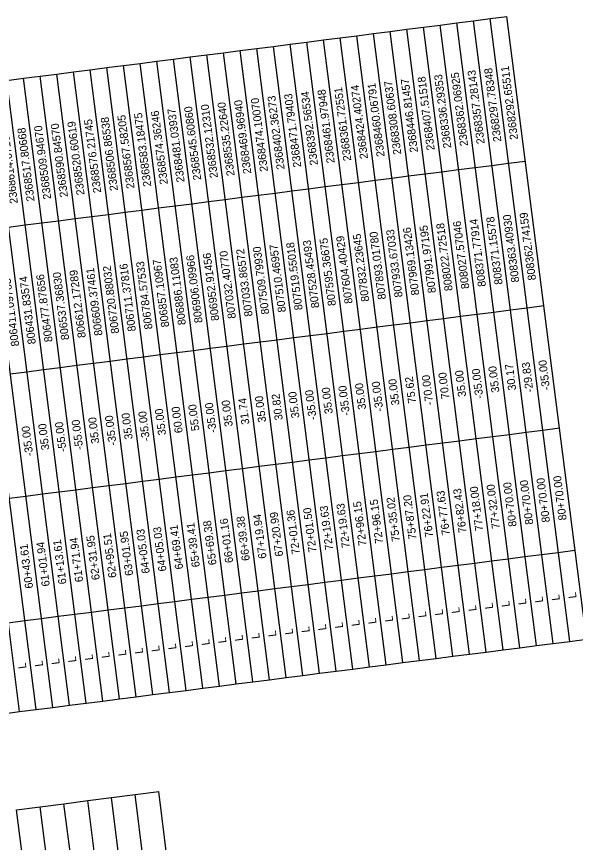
# Model space of a CAD drawing. Extents: x 2364621 to 2374814, y 792603 to 806745.
# Drawn here: x 2369750 to 2371409, y 798784 to 801235 of the extents above; entities that cross this region are included whole.
import ezdxf

# ---------------------------------------------------------------- set-up
doc = ezdxf.new("R2010")
doc.units = 0
doc.layers.add('CTL Sheet Table Cell', color=7, linetype='Continuous')
doc.layers.add('CTL Sheet Text', color=7, linetype='Continuous')

msp = doc.modelspace()

# ---------------------------------------------------------------- linework, layer by layer
at = {"layer": 'CTL Sheet Table Cell'}
for p, q in [((2371106.7, 801222.7), (2371156.1, 801229)), ((2371156.1, 801229), (2371205.6, 801235.3)), ((2371392.1, 799381.2), (2371156.1, 801229)), ((2371441.6, 799387.5), (2371205.6, 801235.3)), ((2370908.7, 801197.4), (2370958.2, 801203.7)), ((2370958.2, 801203.7), (2371007.7, 801210)), ((2371194.2, 799355.9), (2370958.2, 801203.7)), ((2371007.7, 801210), (2371057.2, 801216.3)), ((2371243.7, 799362.2), (2371007.7, 801210)), ((2371057.2, 801216.3), (2371106.7, 801222.7)), ((2371293.2, 799368.6), (2371057.2, 801216.3)), ((2371342.7, 799374.9), (2371106.7, 801222.7)), ((2370710.7, 801172.1), (2370760.2, 801178.4)), ((2370760.2, 801178.4), (2370809.7, 801184.7)), ((2370996.2, 799330.6), (2370760.2, 801178.4)), ((2370809.7, 801184.7), (2370859.2, 801191.1)), ((2371045.7, 799337), (2370809.7, 801184.7)), ((2370859.2, 801191.1), (2370908.7, 801197.4)), ((2371095.2, 799343.3), (2370859.2, 801191.1)), ((2371144.7, 799349.6), (2370908.7, 801197.4)), ((2370562.2, 801153.1), (2370611.7, 801159.4)), ((2370611.7, 801159.4), (2370661.2, 801165.8)), ((2370847.7, 799311.7), (2370611.7, 801159.4)), ((2370661.2, 801165.8), (2370710.7, 801172.1)), ((2370897.2, 799318), (2370661.2, 801165.8)), ((2370946.7, 799324.3), (2370710.7, 801172.1)), ((2370364.2, 801127.8), (2370413.7, 801134.2)), ((2370413.7, 801134.2), (2370463.2, 801140.5)), ((2370649.7, 799286.4), (2370413.7, 801134.2)), ((2370463.2, 801140.5), (2370512.7, 801146.8)), ((2370699.2, 799292.7), (2370463.2, 801140.5)), ((2370512.7, 801146.8), (2370562.2, 801153.1)), ((2370748.7, 799299), (2370512.7, 801146.8)), ((2370798.2, 799305.4), (2370562.2, 801153.1)), ((2370166.3, 801102.6), (2370215.8, 801108.9)), ((2370215.8, 801108.9), (2370265.3, 801115.2)), ((2370451.8, 799261.1), (2370215.8, 801108.9)), ((2370265.3, 801115.2), (2370314.8, 801121.5)), ((2370501.3, 799267.4), (2370265.3, 801115.2)), ((2370314.8, 801121.5), (2370364.2, 801127.8)), ((2370550.7, 799273.7), (2370314.8, 801121.5)), ((2370600.2, 799280.1), (2370364.2, 801127.8)), ((2369968.3, 801077.3), (2370017.8, 801083.6)), ((2370017.8, 801083.6), (2370067.3, 801089.9)), ((2370253.8, 799235.8), (2370017.8, 801083.6)), ((2370067.3, 801089.9), (2370116.8, 801096.2)), ((2370303.3, 799242.1), (2370067.3, 801089.9)), ((2370116.8, 801096.2), (2370166.3, 801102.6)), ((2370352.8, 799248.5), (2370116.8, 801096.2)), ((2370402.3, 799254.8), (2370166.3, 801102.6)), ((2369770.3, 801052), (2369819.8, 801058.3)), ((2369819.8, 801058.3), (2369869.3, 801064.6)), ((2370055.8, 799210.5), (2369819.8, 801058.3)), ((2369869.3, 801064.6), (2369918.8, 801070.9)), ((2370105.3, 799216.9), (2369869.3, 801064.6)), ((2369918.8, 801070.9), (2369968.3, 801077.3)), ((2370154.8, 799223.2), (2369918.8, 801070.9)), ((2370204.3, 799229.5), (2369968.3, 801077.3)), ((2369857.8, 799185.2), (2369621.8, 801033)), ((2369907.3, 799191.6), (2369671.3, 801039.3)), ((2369720.8, 801045.7), (2369770.3, 801052)), ((2369956.8, 799197.9), (2369720.8, 801045.7)), ((2370006.3, 799204.2), (2369770.3, 801052)), ((2369758.8, 799172.6), (2369522.8, 801020.4)), ((2369808.3, 799178.9), (2369572.3, 801026.7)), ((2371062.5, 800781.1), (2371111.9, 800787.4)), ((2371111.9, 800787.4), (2371161.4, 800793.7)), ((2371161.4, 800793.7), (2371210.9, 800800)), ((2371210.9, 800800), (2371260.4, 800806.4)), ((2370864.5, 800755.8), (2370914, 800762.1)), ((2370914, 800762.1), (2370963.5, 800768.4)), ((2370963.5, 800768.4), (2371013, 800774.7)), ((2371013, 800774.7), (2371062.5, 800781.1)), ((2370716, 800736.8), (2370765.5, 800743.1)), ((2370765.5, 800743.1), (2370815, 800749.5)), ((2370815, 800749.5), (2370864.5, 800755.8)), ((2370518, 800711.5), (2370567.5, 800717.9)), ((2370567.5, 800717.9), (2370617, 800724.2)), ((2370617, 800724.2), (2370666.5, 800730.5)), ((2370666.5, 800730.5), (2370716, 800736.8)), ((2370320, 800686.2), (2370369.5, 800692.6)), ((2370369.5, 800692.6), (2370419, 800698.9)), ((2370419, 800698.9), (2370468.5, 800705.2)), ((2370468.5, 800705.2), (2370518, 800711.5)), ((2370122.1, 800661), (2370171.6, 800667.3)), ((2370171.6, 800667.3), (2370221.1, 800673.6)), ((2370221.1, 800673.6), (2370270.5, 800679.9)), ((2370270.5, 800679.9), (2370320, 800686.2)), ((2369924.1, 800635.7), (2369973.6, 800642)), ((2369973.6, 800642), (2370023.1, 800648.3)), ((2370023.1, 800648.3), (2370072.6, 800654.6)), ((2370072.6, 800654.6), (2370122.1, 800661)), ((2369726.1, 800610.4), (2369775.6, 800616.7)), ((2369775.6, 800616.7), (2369825.1, 800623)), ((2369825.1, 800623), (2369874.6, 800629.4)), ((2369874.6, 800629.4), (2369924.1, 800635.7)), ((2371216.2, 800364.8), (2371265.7, 800371.1)), ((2371265.7, 800371.1), (2371315.2, 800377.4)), ((2371018.2, 800339.5), (2371067.7, 800345.8)), ((2371067.7, 800345.8), (2371117.2, 800352.1)), ((2371117.2, 800352.1), (2371166.7, 800358.4)), ((2371166.7, 800358.4), (2371216.2, 800364.8)), ((2370820.3, 800314.2), (2370869.8, 800320.5)), ((2370869.8, 800320.5), (2370919.3, 800326.8)), ((2370919.3, 800326.8), (2370968.8, 800333.2)), ((2370968.8, 800333.2), (2371018.2, 800339.5)), ((2370671.8, 800295.2), (2370721.3, 800301.6)), ((2370721.3, 800301.6), (2370770.8, 800307.9)), ((2370770.8, 800307.9), (2370820.3, 800314.2)), ((2370473.8, 800269.9), (2370523.3, 800276.3)), ((2370523.3, 800276.3), (2370572.8, 800282.6)), ((2370572.8, 800282.6), (2370622.3, 800288.9)), ((2370622.3, 800288.9), (2370671.8, 800295.2)), ((2370275.8, 800244.7), (2370325.3, 800251)), ((2370325.3, 800251), (2370374.8, 800257.3)), ((2370374.8, 800257.3), (2370424.3, 800263.6)), ((2370424.3, 800263.6), (2370473.8, 800269.9)), ((2370077.9, 800219.4), (2370127.4, 800225.7)), ((2370127.4, 800225.7), (2370176.9, 800232)), ((2370176.9, 800232), (2370226.3, 800238.3)), ((2370226.3, 800238.3), (2370275.8, 800244.7)), ((2369879.9, 800194.1), (2369929.4, 800200.4)), ((2369929.4, 800200.4), (2369978.9, 800206.7)), ((2369978.9, 800206.7), (2370028.4, 800213.1)), ((2370028.4, 800213.1), (2370077.9, 800219.4)), ((2369731.4, 800175.1), (2369780.9, 800181.4)), ((2369780.9, 800181.4), (2369830.4, 800187.8)), ((2369830.4, 800187.8), (2369879.9, 800194.1)), ((2371262.6, 800001.8), (2371312.1, 800008.1)), ((2371312.1, 800008.1), (2371361.6, 800014.5)), ((2371064.6, 799976.5), (2371114.1, 799982.8)), ((2371114.1, 799982.8), (2371163.6, 799989.2)), ((2371163.6, 799989.2), (2371213.1, 799995.5)), ((2371213.1, 799995.5), (2371262.6, 800001.8)), ((2370866.6, 799951.2), (2370916.1, 799957.6)), ((2370916.1, 799957.6), (2370965.6, 799963.9)), ((2370965.6, 799963.9), (2371015.1, 799970.2)), ((2371015.1, 799970.2), (2371064.6, 799976.5)), ((2370668.7, 799926), (2370718.1, 799932.3)), ((2370718.1, 799932.3), (2370767.6, 799938.6)), ((2370767.6, 799938.6), (2370817.1, 799944.9)), ((2370817.1, 799944.9), (2370866.6, 799951.2)), ((2370470.7, 799900.7), (2370520.2, 799907)), ((2370520.2, 799907), (2370569.7, 799913.3)), ((2370569.7, 799913.3), (2370619.2, 799919.6)), ((2370619.2, 799919.6), (2370668.7, 799926)), ((2370272.7, 799875.4), (2370322.2, 799881.7)), ((2370322.2, 799881.7), (2370371.7, 799888)), ((2370371.7, 799888), (2370421.2, 799894.3)), ((2370421.2, 799894.3), (2370470.7, 799900.7)), ((2370074.7, 799850.1), (2370124.2, 799856.4)), ((2370124.2, 799856.4), (2370173.7, 799862.7)), ((2370173.7, 799862.7), (2370223.2, 799869.1)), ((2370223.2, 799869.1), (2370272.7, 799875.4)), ((2369876.8, 799824.8), (2369926.2, 799831.1)), ((2369926.2, 799831.1), (2369975.7, 799837.5)), ((2369975.7, 799837.5), (2370025.2, 799843.8)), ((2370025.2, 799843.8), (2370074.7, 799850.1)), ((2369728.3, 799805.8), (2369777.8, 799812.2)), ((2369777.8, 799812.2), (2369827.3, 799818.5)), ((2369827.3, 799818.5), (2369876.8, 799824.8)), ((2371259.4, 799632.5), (2371308.9, 799638.9)), ((2371308.9, 799638.9), (2371358.4, 799645.2)), ((2371358.4, 799645.2), (2371407.9, 799651.5)), ((2371061.5, 799607.2), (2371111, 799613.6)), ((2371111, 799613.6), (2371160.5, 799619.9)), ((2371160.5, 799619.9), (2371209.9, 799626.2)), ((2371209.9, 799626.2), (2371259.4, 799632.5)), ((2370863.5, 799582), (2370913, 799588.3)), ((2370913, 799588.3), (2370962.5, 799594.6)), ((2370962.5, 799594.6), (2371012, 799600.9)), ((2371012, 799600.9), (2371061.5, 799607.2)), ((2370665.5, 799556.7), (2370715, 799563)), ((2370715, 799563), (2370764.5, 799569.3)), ((2370764.5, 799569.3), (2370814, 799575.6)), ((2370814, 799575.6), (2370863.5, 799582)), ((2370467.5, 799531.4), (2370517, 799537.7)), ((2370517, 799537.7), (2370566.5, 799544)), ((2370566.5, 799544), (2370616, 799550.4)), ((2370616, 799550.4), (2370665.5, 799556.7)), ((2370269.6, 799506.1), (2370319.1, 799512.4)), ((2370319.1, 799512.4), (2370368.6, 799518.7)), ((2370368.6, 799518.7), (2370418, 799525.1)), ((2370418, 799525.1), (2370467.5, 799531.4)), ((2370121.1, 799487.1), (2370170.6, 799493.5)), ((2370170.6, 799493.5), (2370220.1, 799499.8)), ((2370220.1, 799499.8), (2370269.6, 799506.1)), ((2369923.1, 799461.9), (2369972.6, 799468.2)), ((2369972.6, 799468.2), (2370022.1, 799474.5)), ((2370022.1, 799474.5), (2370071.6, 799480.8)), ((2370071.6, 799480.8), (2370121.1, 799487.1)), ((2369725.1, 799436.6), (2369774.6, 799442.9)), ((2369774.6, 799442.9), (2369824.1, 799449.2)), ((2369824.1, 799449.2), (2369873.6, 799455.5)), ((2369873.6, 799455.5), (2369923.1, 799461.9)), ((2371243.7, 799362.2), (2371293.2, 799368.6)), ((2371293.2, 799368.6), (2371342.7, 799374.9)), ((2371342.7, 799374.9), (2371392.1, 799381.2)), ((2371392.1, 799381.2), (2371441.6, 799387.5)), ((2371045.7, 799337), (2371095.2, 799343.3)), ((2371095.2, 799343.3), (2371144.7, 799349.6)), ((2371144.7, 799349.6), (2371194.2, 799355.9)), ((2371194.2, 799355.9), (2371243.7, 799362.2)), ((2370847.7, 799311.7), (2370897.2, 799318)), ((2370897.2, 799318), (2370946.7, 799324.3)), ((2370946.7, 799324.3), (2370996.2, 799330.6)), ((2370996.2, 799330.6), (2371045.7, 799337)), ((2370649.7, 799286.4), (2370699.2, 799292.7)), ((2370699.2, 799292.7), (2370748.7, 799299)), ((2370748.7, 799299), (2370798.2, 799305.4)), ((2370798.2, 799305.4), (2370847.7, 799311.7)), ((2370451.8, 799261.1), (2370501.3, 799267.4)), ((2370501.3, 799267.4), (2370550.7, 799273.7)), ((2370550.7, 799273.7), (2370600.2, 799280.1)), ((2370600.2, 799280.1), (2370649.7, 799286.4)), ((2370253.8, 799235.8), (2370303.3, 799242.1)), ((2370303.3, 799242.1), (2370352.8, 799248.5)), ((2370352.8, 799248.5), (2370402.3, 799254.8)), ((2370402.3, 799254.8), (2370451.8, 799261.1)), ((2370105.3, 799216.9), (2370154.8, 799223.2)), ((2370154.8, 799223.2), (2370204.3, 799229.5)), ((2370204.3, 799229.5), (2370253.8, 799235.8)), ((2369907.3, 799191.6), (2369956.8, 799197.9)), ((2369956.8, 799197.9), (2370006.3, 799204.2)), ((2370006.3, 799204.2), (2370055.8, 799210.5)), ((2370055.8, 799210.5), (2370105.3, 799216.9)), ((2369709.4, 799166.3), (2369758.8, 799172.6)), ((2369758.8, 799172.6), (2369808.3, 799178.9)), ((2369808.3, 799178.9), (2369857.8, 799185.2)), ((2369857.8, 799185.2), (2369907.3, 799191.6)), ((2370031.5, 798917.4), (2370101.8, 798926.4)), ((2370101.8, 798926.4), (2370172.1, 798935.4)), ((2370353.2, 796957.9), (2370101.8, 798926.4)), ((2370423.5, 796966.9), (2370172.1, 798935.4)), ((2369820.6, 798890.5), (2369890.9, 798899.5)), ((2369890.9, 798899.5), (2369961.2, 798908.5)), ((2370142.3, 796931), (2369890.9, 798899.5)), ((2369961.2, 798908.5), (2370031.5, 798917.4)), ((2370212.6, 796939.9), (2369961.2, 798908.5)), ((2370282.9, 796948.9), (2370031.5, 798917.4)), ((2369750.3, 798881.5), (2369820.6, 798890.5)), ((2370001.7, 796913), (2369750.3, 798881.5)), ((2370072, 796922), (2369820.6, 798890.5))]:
    msp.add_line(p, q, dxfattribs=at)

# ---------------------------------------------------------------- texts
at = {"layer": 'CTL Sheet Text'}
for s, height, p in [('2368297.78348', 23.76, (2371189.5, 800864.8)), ('2368292.65511', 23.76, (2371239, 800871.1)), ('2368407.51518', 23.76, (2370991.5, 800839.5)), ('2368336.29353', 23.76, (2371041, 800845.8)), ('2368362.06925', 23.76, (2371090.5, 800852.1)), ('2368357.28143', 23.76, (2371140, 800858.4)), ('2368424.40274', 23.76, (2370793.5, 800814.2)), ('2368460.06791', 23.76, (2370843, 800820.5)), ('2368308.60637', 23.76, (2370892.5, 800826.8)), ('2368446.81457', 23.76, (2370942, 800833.2)), ('2368392.56534', 23.76, (2370645.1, 800795.2)), ('2368461.97948', 23.76, (2370694.6, 800801.5)), ('2368361.72551', 23.76, (2370744, 800807.9)), ('2368469.96940', 23.76, (2370447.1, 800769.9)), ('2368474.10070', 23.76, (2370496.6, 800776.3)), ('2368402.36273', 23.76, (2370546.1, 800782.6)), ('2368471.79403', 23.76, (2370595.6, 800788.9)), ('2368481.03937', 23.76, (2370249.1, 800744.7)), ('2368545.60860', 23.76, (2370298.6, 800751)), ('2368532.12310', 23.76, (2370348.1, 800757.3)), ('2368535.22640', 23.76, (2370397.6, 800763.6)), ('2368506.86538', 23.76, (2370051.1, 800719.4)), ('2368567.58205', 23.76, (2370100.6, 800725.7)), ('2368583.18475', 23.76, (2370150.1, 800732)), ('2368574.36246', 23.76, (2370199.6, 800738.3)), ('2368509.94670', 23.76, (2369853.2, 800694.1)), ('2368590.84570', 23.76, (2369902.7, 800700.4)), ('2368520.60619', 23.76, (2369952.1, 800706.7)), ('2368576.21745', 23.76, (2370001.6, 800713)), ('2368614.67163', 23.76, (2369754.2, 800681.4)), ('2368517.80668', 23.76, (2369803.7, 800687.8)), ('808371.15578', 23.76, (2371193.3, 800441.2)), ('808363.40930', 23.76, (2371242.8, 800447.5)), ('808362.74159', 23.76, (2371292.3, 800453.8)), ('807991.97195', 23.76, (2370995.3, 800415.9)), ('808022.72518', 23.76, (2371044.8, 800422.2)), ('808027.57046', 23.76, (2371094.3, 800428.5)), ('808371.77914', 23.76, (2371143.8, 800434.9)), ('807832.23645', 23.76, (2370797.3, 800390.6)), ('807893.01780', 23.76, (2370846.8, 800396.9)), ('807933.67033', 23.76, (2370896.3, 800403.3)), ('807969.13426', 23.76, (2370945.8, 800409.6)), ('807528.45493', 23.76, (2370648.9, 800371.6)), ('807595.36675', 23.76, (2370698.4, 800378)), ('807604.40429', 23.76, (2370747.8, 800384.3)), ('807033.86572', 23.76, (2370450.9, 800346.4)), ('807509.79930', 23.76, (2370500.4, 800352.7)), ('807510.46957', 23.76, (2370549.9, 800359)), ('807519.55018', 23.76, (2370599.4, 800365.3)), ('806886.11083', 23.76, (2370252.9, 800321.1)), ('806906.09966', 23.76, (2370302.4, 800327.4)), ('806952.91456', 23.76, (2370351.9, 800333.7)), ('807032.40770', 23.76, (2370401.4, 800340)), ('806720.88032', 23.76, (2370054.9, 800295.8)), ('806711.37816', 23.76, (2370104.4, 800302.1)), ('806784.57533', 23.76, (2370153.9, 800308.4)), ('806857.10967', 23.76, (2370203.4, 800314.8)), ('806477.87656', 23.76, (2369857, 800270.5)), ('806537.36830', 23.76, (2369906.4, 800276.8)), ('806612.17289', 23.76, (2369955.9, 800283.1)), ('806609.37461', 23.76, (2370005.4, 800289.5)), ('806411.09763', 23.76, (2369758, 800257.9)), ('806431.83574', 23.76, (2369807.5, 800264.2)), ('30.17', 23.76, (2371233.4, 800127.1)), ('-29.83', 23.76, (2371284.4, 800121.7)), ('-35.00', 23.76, (2371333.9, 800128)), ('70.00', 23.76, (2371035.4, 800101.8)), ('35.00', 23.76, (2371084.9, 800108.1)), ('-35.00', 23.76, (2371135.9, 800102.7)), ('35.00', 23.76, (2371183.9, 800120.7)), ('-35.00', 23.76, (2370839, 800064.8)), ('35.00', 23.76, (2370887, 800082.8)), ('75.62', 23.76, (2370936.4, 800089.1)), ('-70.00', 23.76, (2370987.4, 800083.8)), ('-35.00', 23.76, (2370641, 800039.5)), ('35.00', 23.76, (2370689, 800057.5)), ('-35.00', 23.76, (2370740, 800052.2)), ('35.00', 23.76, (2370788, 800070.2)), ('31.74', 23.76, (2370441.5, 800025.9)), ('35.00', 23.76, (2370491, 800032.3)), ('30.82', 23.76, (2370540.5, 800038.6)), ('35.00', 23.76, (2370590, 800044.9)), ('60.00', 23.76, (2370243.5, 800000.6)), ('55.00', 23.76, (2370293, 800007)), ('-35.00', 23.76, (2370344, 800001.6)), ('35.00', 23.76, (2370392, 800019.6)), ('-35.00', 23.76, (2370047, 799963.7)), ('35.00', 23.76, (2370095, 799981.7)), ('-35.00', 23.76, (2370146, 799976.3)), ('35.00', 23.76, (2370194, 799994.3)), ('35.00', 23.76, (2369847.6, 799950.1)), ('-55.00', 23.76, (2369898.6, 799944.7)), ('-55.00', 23.76, (2369948.1, 799951)), ('35.00', 23.76, (2369996.1, 799969)), ('-35.00', 23.76, (2369799.6, 799932.1)), ('80+70.00', 23.76, (2371284.2, 799729)), ('80+70.00', 23.76, (2371333.7, 799735.4)), ('80+70.00', 23.76, (2371383.2, 799741.7)), ('76+82.43', 23.76, (2371086.3, 799703.8)), ('77+18.00', 23.76, (2371135.8, 799710.1)), ('77+32.00', 23.76, (2371185.3, 799716.4)), ('80+70.00', 23.76, (2371234.8, 799722.7)), ('75+35.02', 23.76, (2370888.3, 799678.5)), ('75+87.20', 23.76, (2370937.8, 799684.8)), ('76+22.91', 23.76, (2370987.3, 799691.1)), ('76+77.63', 23.76, (2371036.8, 799697.4)), ('72+19.63', 23.76, (2370690.3, 799653.2)), ('72+19.63', 23.76, (2370739.8, 799659.5)), ('72+96.15', 23.76, (2370789.3, 799665.8)), ('72+96.15', 23.76, (2370838.8, 799672.1)), ('67+19.94', 23.76, (2370492.3, 799627.9)), ('67+20.99', 23.76, (2370541.8, 799634.2)), ('72+01.36', 23.76, (2370591.3, 799640.5)), ('72+01.50', 23.76, (2370640.8, 799646.9)), ('65+39.41', 23.76, (2370294.4, 799602.6)), ('65+69.38', 23.76, (2370343.9, 799608.9)), ('66+01.16', 23.76, (2370393.4, 799615.3)), ('66+39.38', 23.76, (2370442.8, 799621.6)), ('63+01.95', 23.76, (2370096.4, 799577.3)), ('64+05.03', 23.76, (2370145.9, 799583.7)), ('64+05.03', 23.76, (2370195.4, 799590)), ('64+69.41', 23.76, (2370244.9, 799596.3)), ('61+71.94', 23.76, (2369947.9, 799558.4)), ('62+31.95', 23.76, (2369997.4, 799564.7)), ('62+95.51', 23.76, (2370046.9, 799571)), ('60+43.61', 23.76, (2369799.4, 799539.4)), ('61+01.94', 23.76, (2369848.9, 799545.7)), ('61+13.61', 23.76, (2369898.4, 799552)), ('L', 23.8, (2371313.8, 799497.4)), ('L', 23.8, (2371363.3, 799503.7)), ('L', 23.8, (2371412.8, 799510.1)), ('L', 23.8, (2371115.9, 799472.1)), ('L', 23.8, (2371165.3, 799478.5)), ('L', 23.8, (2371214.8, 799484.8)), ('L', 23.8, (2371264.3, 799491.1)), ('L', 23.8, (2370917.9, 799446.8)), ('L', 23.8, (2370967.4, 799453.2)), ('L', 23.8, (2371016.9, 799459.5)), ('L', 23.8, (2371066.4, 799465.8)), ('L', 23.8, (2370769.4, 799427.9)), ('L', 23.8, (2370818.9, 799434.2)), ('L', 23.8, (2370868.4, 799440.5)), ('L', 23.8, (2370571.4, 799402.6)), ('L', 23.8, (2370620.9, 799408.9)), ('L', 23.8, (2370670.4, 799415.2)), ('L', 23.8, (2370719.9, 799421.6)), ('L', 23.8, (2370373.4, 799377.3)), ('L', 23.8, (2370422.9, 799383.6)), ('L', 23.8, (2370472.4, 799390)), ('L', 23.8, (2370521.9, 799396.3)), ('L', 23.8, (2370175.5, 799352)), ('L', 23.8, (2370225, 799358.4)), ('L', 23.8, (2370274.5, 799364.7)), ('L', 23.8, (2370323.9, 799371)), ('L', 23.8, (2369977.5, 799326.7)), ('L', 23.8, (2370027, 799333.1)), ('L', 23.8, (2370076.5, 799339.4)), ('L', 23.8, (2370126, 799345.7)), ('L', 23.8, (2369779.5, 799301.5)), ('L', 23.8, (2369829, 799307.8)), ('L', 23.8, (2369878.5, 799314.1)), ('L', 23.8, (2369928, 799320.4))]:
    msp.add_text(s, height=height, rotation=97.2784, dxfattribs=at).set_placement(p)

doc.saveas('drawing.dxf')
